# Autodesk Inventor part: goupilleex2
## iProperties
Created: 2006-05
Part Number: goupilleex2
Document SubType Name: Modeling
Designer: Administrateur
Manufacturer: Standard
Standards Organization: Custom
Author: Administrateur
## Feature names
1. Extrusion1
2. Chanfrein1 [Chamfer]
